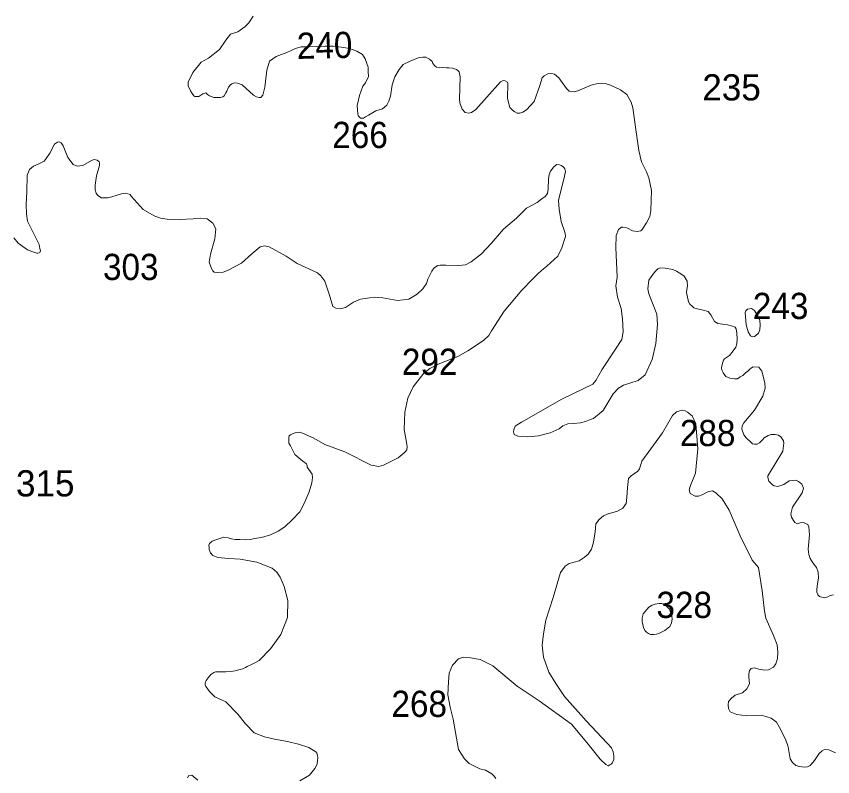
# Model space of a CAD drawing. Extents: x 445.4 to 500, y 8728.7 to 8784.
# Drawn here: x 471.621 to 476.604, y 8779.353 to 8783.996 of the extents above; entities that cross this region are included whole.
import ezdxf
from ezdxf.enums import TextEntityAlignment as Align

# ---------------------------------------------------------------- set-up
doc = ezdxf.new("R2010")
doc.units = 0
doc.header["$LTSCALE"] = 0.064
doc.layers.add('2', color=7, linetype='Continuous', lineweight=13)
doc.layers.add('21', color=7, linetype='Continuous')
doc.layers.add('61', color=7, linetype='Continuous')

msp = doc.modelspace()

# ---------------------------------------------------------------- linework, layer by layer
at = {"layer": '2'}
for points in [[(473.0668, 8783.9956), (473.0406, 8783.9568), (473.0151, 8783.9313), (472.9726, 8783.9016), (472.9286, 8783.8861), (472.8989, 8783.8493), (472.8606, 8783.7927), (472.7941, 8783.7403), (472.7501, 8783.7162), (472.6991, 8783.6526), (472.6708, 8783.5946), (472.6708, 8783.5719), (472.6835, 8783.5408), (472.6949, 8783.5252), (472.7034, 8783.5111), (472.7105, 8783.5068), (472.7345, 8783.5068), (472.7602, 8783.5219), (472.7772, 8783.5276), (472.7885, 8783.5177), (472.7999, 8783.5106), (472.8268, 8783.4993), (472.8452, 8783.4993), (472.8679, 8783.5007), (472.8806, 8783.505), (472.8891, 8783.5106), (472.8891, 8783.5106), (472.9004, 8783.5276), (472.9061, 8783.5389), (472.916, 8783.563), (472.9274, 8783.5771), (472.9359, 8783.5842), (472.9529, 8783.5899), (472.9699, 8783.587), (472.9699, 8783.587), (472.9996, 8783.5771), (473.069, 8783.5135), (473.086, 8783.505), (473.1002, 8783.5007), (473.1129, 8783.4993), (473.1257, 8783.5135), (473.1384, 8783.563), (473.1498, 8783.6663), (473.1668, 8783.7215), (473.2065, 8783.7512), (473.2716, 8783.7738), (473.3259, 8783.7987), (473.3585, 8783.8086), (473.3996, 8783.8086), (473.4506, 8783.8114), (473.5058, 8783.8143), (473.5554, 8783.8143), (473.6064, 8783.8072), (473.6546, 8783.7987), (473.6985, 8783.7831), (473.7339, 8783.7619), (473.7509, 8783.7365), (473.7686, 8783.6846), (473.7686, 8783.6578), (473.77, 8783.628), (473.7516, 8783.5898), (473.736, 8783.5686), (473.7162, 8783.512), (473.702, 8783.4512), (473.7062, 8783.3974), (473.7091, 8783.3861), (473.7218, 8783.3733), (473.7402, 8783.3747), (473.7516, 8783.3818), (473.7714, 8783.3917), (473.8153, 8783.4186), (473.855, 8783.4313), (473.8833, 8783.454), (473.8947, 8783.4766), (473.9046, 8783.5078), (473.9159, 8783.5771), (473.9315, 8783.6266), (473.9584, 8783.6719), (473.9825, 8783.7016), (474.025, 8783.7214), (474.0746, 8783.7413), (474.1015, 8783.7455), (474.1199, 8783.7455), (474.1426, 8783.7342), (474.1582, 8783.72), (474.1638, 8783.7073), (474.1752, 8783.6931), (474.1865, 8783.6846), (474.2035, 8783.6804), (474.2219, 8783.6832), (474.246, 8783.6818), (474.2616, 8783.6818), (474.2828, 8783.679), (474.3083, 8783.6705), (474.3083, 8783.6705), (474.3183, 8783.6634), (474.3239, 8783.6563), (474.3306, 8783.6262), (474.3249, 8783.489), (474.3277, 8783.4678), (474.3419, 8783.4281)], [(474.3419, 8783.4281), (474.3603, 8783.4083), (474.383, 8783.4041), (474.3986, 8783.4083), (474.4255, 8783.4267), (474.5757, 8783.5965), (474.5757, 8783.5965), (474.5927, 8783.6036), (474.6054, 8783.6008), (474.6182, 8783.5937), (474.621, 8783.5866), (474.6182, 8783.4932), (474.6337, 8783.438), (474.6465, 8783.4253), (474.6592, 8783.4154), (474.6777, 8783.4041), (474.6947, 8783.4041), (474.7131, 8783.4097), (474.7357, 8783.4253), (474.7811, 8783.4762), (474.8165, 8783.5725), (474.8307, 8783.6206), (474.8434, 8783.6319), (474.8647, 8783.6446), (474.8882, 8783.6462), (474.9066, 8783.6434), (474.9321, 8783.6194), (474.9789, 8783.5557), (474.9959, 8783.5387), (474.9959, 8783.5387), (475.0256, 8783.5345), (475.0483, 8783.5415), (475.1304, 8783.5755), (475.163, 8783.584), (475.1914, 8783.5882), (475.214, 8783.5854), (475.2466, 8783.5755), (475.3089, 8783.5472), (475.3472, 8783.5175), (475.3741, 8783.4722), (475.3829, 8783.4374), (475.4041, 8783.2903), (475.4197, 8783.1756), (475.4367, 8783.1063), (475.4665, 8783.0469), (475.481, 8783.0105), (475.498, 8782.9313), (475.4937, 8782.811), (475.4866, 8782.7742), (475.4668, 8782.7346), (475.4413, 8782.6936), (475.4328, 8782.6865), (475.4101, 8782.6822), (475.3818, 8782.6851), (475.3506, 8782.702), (475.3421, 8782.7063), (475.3237, 8782.7091), (475.3138, 8782.7077), (475.2954, 8782.6936), (475.2826, 8782.6568), (475.281, 8782.5836), (475.2881, 8782.4025), (475.2796, 8782.3501), (475.2895, 8782.2808), (475.3122, 8782.2114), (475.3207, 8782.148), (475.325, 8782.0702), (475.3165, 8782.0235), (475.2782, 8781.9627), (475.1947, 8781.8367), (475.1578, 8781.773), (475.1388, 8781.7507), (474.9504, 8781.6588), (474.7039, 8781.5173), (474.6656, 8781.4932), (474.6585, 8781.4706), (474.6557, 8781.4578), (474.6595, 8781.4431), (474.6595, 8781.4431), (474.6828, 8781.4314), (474.7412, 8781.4285), (474.8083, 8781.4343), (474.8784, 8781.4518), (474.9338, 8781.4781), (474.9572, 8781.4956), (474.9864, 8781.5072), (475.0214, 8781.5101), (475.0651, 8781.5131), (475.0943, 8781.5218), (475.1264, 8781.5335), (475.1439, 8781.5393), (475.2023, 8781.5888), (475.2636, 8781.6909), (475.2957, 8781.7259), (475.3278, 8781.743), (475.4166, 8781.7731), (475.4595, 8781.8064), (475.5023, 8781.9014), (475.5234, 8781.9974), (475.5345, 8782.1147), (475.5297, 8782.1765)], [(474.3217, 8782.4741), (474.243, 8782.4754), (474.2082, 8782.4767), (474.1927, 8782.4741), (474.1707, 8782.46), (474.1565, 8782.4406), (474.1333, 8782.3903), (474.1251, 8782.3643), (474.1031, 8782.332), (474.0683, 8782.2998), (474.0166, 8782.2689), (473.9482, 8782.2599), (473.8579, 8782.2766), (473.8101, 8782.2805), (473.7779, 8782.2779), (473.7211, 8782.2689), (473.6798, 8782.2495), (473.6295, 8782.2186), (473.5985, 8782.2096), (473.5714, 8782.2134), (473.552, 8782.2238), (473.5314, 8782.2985), (473.5046, 8782.3788), (473.4788, 8782.411), (473.4582, 8782.4303), (473.3343, 8782.487), (473.2672, 8782.5309), (473.1639, 8782.5889), (473.1381, 8782.5953), (473.1097, 8782.5889), (473.0581, 8782.5451), (472.9961, 8782.4883), (472.9097, 8782.4432), (472.8833, 8782.4343), (472.8497, 8782.4318), (472.8278, 8782.433), (472.82, 8782.4408), (472.8123, 8782.455), (472.7981, 8782.4949), (472.8071, 8782.5439), (472.8316, 8782.6367), (472.8381, 8782.6981), (472.82, 8782.7329), (472.7865, 8782.7587), (472.7439, 8782.7626), (472.7013, 8782.76), (472.6161, 8782.7561), (472.5419, 8782.7564), (472.5019, 8782.7629), (472.4619, 8782.7771), (472.3961, 8782.817), (472.3225, 8782.897), (472.3148, 8782.9086), (472.2864, 8782.9163), (472.2631, 8782.9124), (472.2038, 8782.8944), (472.1779, 8782.8879), (472.14, 8782.8871), (472.1193, 8782.9025), (472.109, 8782.9154), (472.1025, 8782.9361), (472.1025, 8782.9644), (472.1103, 8783.0224), (472.1284, 8783.0843), (472.1284, 8783.0985), (472.1271, 8783.1062), (472.1142, 8783.1178), (472.0961, 8783.1217), (472.0793, 8783.1153), (472.0277, 8783.0843), (472.0083, 8783.083), (471.9915, 8783.0817), (471.9683, 8783.0908), (471.9361, 8783.1346), (471.9064, 8783.2042), (471.8948, 8783.2235), (471.8818, 8783.2287), (471.8715, 8783.2274), (471.8715, 8783.2274), (471.8543, 8783.2158), (471.8246, 8783.1603), (471.8039, 8783.1268), (471.791, 8783.1113), (471.7536, 8783.0933), (471.7265, 8783.0817), (471.702, 8783.0598), (471.6865, 8783.0263), (471.6852, 8782.9231), (471.6813, 8782.8462), (471.6826, 8782.7895), (471.689, 8782.7444), (471.711, 8782.6993), (471.7394, 8782.6425), (471.7613, 8782.6026), (471.7639, 8782.5781), (471.7677, 8782.5639), (471.7671, 8782.5573), (471.7651, 8782.5537), (471.7605, 8782.5507), (471.7528, 8782.5496), (471.7452, 8782.5496)], [(472.8438, 8780.8024), (472.8878, 8780.8157), (472.9145, 8780.8116), (472.9339, 8780.8045), (472.9565, 8780.8024), (472.9851, 8780.8024), (473.0189, 8780.8004), (473.0497, 8780.8024), (473.0753, 8780.8076), (473.1173, 8780.8127), (473.1726, 8780.8301), (473.2194, 8780.8521), (473.2604, 8780.8787), (473.3054, 8780.9206), (473.3505, 8780.9708), (473.3782, 8781.0219), (473.4089, 8781.0925), (473.4243, 8781.1478), (473.4285, 8781.1802), (473.4264, 8781.1996), (473.3967, 8781.2436), (473.3967, 8781.2508), (473.3937, 8781.2569), (473.3916, 8781.2641), (473.3691, 8781.2794), (473.3199, 8781.3214), (473.2953, 8781.3736), (473.2851, 8781.3899), (473.2851, 8781.4237), (473.2861, 8781.4339), (473.2943, 8781.4411), (473.3066, 8781.4472), (473.322, 8781.4534), (473.3342, 8781.4554), (473.3486, 8781.4564), (473.367, 8781.4503), (473.4367, 8781.4196), (473.5043, 8781.3807), (473.6262, 8781.3367), (473.787, 8781.2559), (473.8329, 8781.2462), (473.8482, 8781.2503), (473.8626, 8781.2544), (473.9518, 8781.2991), (473.9877, 8781.3298), (473.999, 8781.34), (474.0041, 8781.3492), (474.0061, 8781.3666), (474.0051, 8781.384), (473.9877, 8781.473), (473.9918, 8781.5782), (474.0102, 8781.6652), (474.044, 8781.7337), (474.1085, 8781.8166), (474.1457, 8781.8458), (474.2051, 8781.8765), (474.3158, 8781.9195), (474.3772, 8781.9543), (474.4725, 8782.0167), (474.5042, 8782.0474), (474.5221, 8782.0747), (474.5989, 8782.1965), (474.7065, 8782.3244), (474.7734, 8782.3926), (474.8061, 8782.4254), (474.8246, 8782.4418), (474.8379, 8782.453), (474.8584, 8782.4694), (474.927, 8782.5308), (474.9506, 8782.5819), (474.9732, 8782.6504), (474.9706, 8782.6711), (474.9461, 8782.7433), (474.9332, 8782.818), (474.9293, 8782.8709), (474.9435, 8782.9302), (474.9628, 8783.0011), (474.9719, 8783.0483), (474.9694, 8783.0638), (474.9655, 8783.0715), (474.9564, 8783.078), (474.9474, 8783.0844), (474.9358, 8783.0896), (474.919, 8783.0909), (474.9022, 8783.0767), (474.8816, 8783.0509), (474.8738, 8783.0303), (474.87, 8783.0006), (474.8674, 8782.9426), (474.8635, 8782.913), (474.848, 8782.8962), (474.8287, 8782.8807), (474.7998, 8782.8592), (474.7352, 8782.8244), (474.6733, 8782.7638), (474.5946, 8782.6968), (474.5197, 8782.6079), (474.4598, 8782.545), (474.3966, 8782.4973), (474.363, 8782.4793), (474.3217, 8782.4741)], [(471.7452, 8782.5496), (471.7217, 8782.5573), (471.6884, 8782.5701), (471.6322, 8782.6104), (471.6049, 8782.6433)], [(475.5297, 8782.1765), (475.4806, 8782.3017), (475.4745, 8782.3325), (475.4824, 8782.3848), (475.4999, 8782.4118), (475.5221, 8782.4387), (475.5364, 8782.4545), (475.5507, 8782.4609), (475.5808, 8782.4577), (475.6284, 8782.4498), (475.6506, 8782.4387), (475.6776, 8782.4228), (475.6966, 8782.4086), (475.7157, 8782.3785), (475.7172, 8782.35), (475.7141, 8782.3278), (475.7109, 8782.3103), (475.722, 8782.2628), (475.7236, 8782.2533), (475.7315, 8782.2374), (475.7458, 8782.2264), (475.7569, 8782.2153), (475.7775, 8782.2105), (475.7966, 8782.2058), (475.814, 8782.2026), (475.8442, 8782.1931), (475.8605, 8782.1729), (475.8827, 8782.1317), (475.9033, 8782.1206), (475.9319, 8782.1159), (475.962, 8782.1111), (475.9922, 8782.1048), (476.008, 8782.0984), (476.0144, 8782.0874), (476.0176, 8782.062), (476.0207, 8782.0256), (476.0176, 8781.9954), (476.0128, 8781.9764), (475.9969, 8781.9527), (475.9731, 8781.9257), (475.943, 8781.9035), (475.9366, 8781.8956), (475.9335, 8781.8845), (475.9271, 8781.8623), (475.9255, 8781.8481), (475.9287, 8781.8306), (475.9351, 8781.8196), (475.9509, 8781.7974), (475.9763, 8781.7863), (475.9938, 8781.7847), (476.0049, 8781.7815), (476.0223, 8781.7831), (476.0302, 8781.7879), (476.0398, 8781.7942), (476.0556, 8781.8037), (476.0715, 8781.818), (476.0858, 8781.8291), (476.0985, 8781.8417), (476.108, 8781.8497), (476.1191, 8781.856), (476.1524, 8781.8544), (476.1524, 8781.8544), (476.1714, 8781.8291), (476.1905, 8781.7578), (476.1923, 8781.7249), (476.1764, 8781.6758), (476.1272, 8781.5918), (476.0622, 8781.5142), (476.0511, 8781.4951), (476.0495, 8781.4745), (476.0606, 8781.4413), (476.0749, 8781.4223), (476.105, 8781.3953), (476.1146, 8781.3858), (476.1257, 8781.3826), (476.1431, 8781.3842), (476.1574, 8781.3921), (476.1748, 8781.4096), (476.1859, 8781.4223), (476.2097, 8781.4365), (476.2272, 8781.4429), (476.2526, 8781.4429), (476.2732, 8781.4381), (476.2875, 8781.4286), (476.3033, 8781.4048), (476.3049, 8781.389), (476.2986, 8781.3399), (476.2529, 8781.2628), (476.2085, 8781.1899), (476.2069, 8781.1804), (476.2148, 8781.1582), (476.2355, 8781.136), (476.2466, 8781.1297), (476.2688, 8781.1249), (476.3053, 8781.1376), (476.3386, 8781.1598), (476.3782, 8781.1629), (476.3957, 8781.155), (476.4163, 8781.1392), (476.4258, 8781.1154), (476.4179, 8781.0869)], [(475.9718, 8780.9796), (475.9282, 8781.0498), (475.8894, 8781.0861), (475.87, 8781.0982), (475.8409, 8781.0934), (475.807, 8781.074), (475.7852, 8781.0667), (475.7634, 8781.0667), (475.7343, 8781.0813), (475.727, 8781.1055), (475.7367, 8781.1321), (475.7658, 8781.2072), (475.7801, 8781.3541), (475.7682, 8781.508), (475.7454, 8781.5563), (475.717, 8781.579), (475.7042, 8781.5876), (475.6842, 8781.5904), (475.67, 8781.5862), (475.6501, 8781.5805), (475.6259, 8781.5591), (475.5647, 8781.4525), (475.438, 8781.2805), (475.4323, 8781.2592), (475.4252, 8781.2336), (475.4152, 8781.2194), (475.374, 8781.1909), (475.3583, 8781.1739), (475.3512, 8781.1184), (475.348, 8781.0576), (475.3423, 8781.022), (475.3224, 8780.9922), (475.2896, 8780.9737), (475.227, 8780.9566), (475.2042, 8780.9453), (475.1786, 8780.9239), (475.1587, 8780.8969), (475.153, 8780.8486), (475.143, 8780.7846), (475.1316, 8780.742), (475.1117, 8780.7121), (475.0875, 8780.6908), (475.0557, 8780.6712), (474.9959, 8780.6542), (474.9717, 8780.6385), (474.9418, 8780.6002), (474.8977, 8780.448), (474.8536, 8780.3087), (474.8379, 8780.2254), (474.8307, 8780.1572), (474.8379, 8780.0833), (474.872, 8779.9923), (474.9147, 8779.9226), (474.966, 8779.842), (475.0998, 8779.6942), (475.2279, 8779.5577), (475.2535, 8779.5299), (475.2635, 8779.5058), (475.2677, 8779.4816), (475.2677, 8779.4589), (475.2578, 8779.4361), (475.2507, 8779.4304), (475.2435, 8779.4247), (475.2336, 8779.4205), (475.2194, 8779.4276), (475.1838, 8779.4603), (475.1026, 8779.5626), (475.0087, 8779.675), (474.8119, 8779.8167), (474.6781, 8779.9063), (474.5301, 8780.03), (474.4518, 8780.0683), (474.3921, 8780.0797), (474.3479, 8780.084), (474.3195, 8780.0726), (474.2839, 8780.0342), (474.2625, 8779.9845), (474.2583, 8779.9319), (474.2554, 8779.8523), (474.2696, 8779.7783), (474.2863, 8779.7036), (474.3076, 8779.5885), (474.3204, 8779.5202), (474.3574, 8779.4619), (474.3845, 8779.4335), (474.45, 8779.4008), (474.4855, 8779.3923), (474.5225, 8779.371), (474.5368, 8779.3557), (474.5468, 8779.3429)], [(476.4179, 8781.0869), (476.3592, 8780.9981), (476.3513, 8780.9744), (476.3481, 8780.9585), (476.3529, 8780.9379), (476.364, 8780.9173), (476.3735, 8780.9046), (476.3862, 8780.8967), (476.4052, 8780.9031), (476.4258, 8780.9046), (476.4258, 8780.9046), (476.4385, 8780.8999), (476.4385, 8780.8999), (476.4512, 8780.892), (476.4576, 8780.8793), (476.4625, 8780.8304), (476.453, 8780.7433), (476.4582, 8780.7098), (476.4669, 8780.6846), (476.4815, 8780.6584), (476.5039, 8780.6312), (476.5155, 8780.603), (476.5165, 8780.5661), (476.5097, 8780.5185), (476.5078, 8780.4923), (476.5078, 8780.4806), (476.5136, 8780.4632), (476.5223, 8780.4544), (476.5291, 8780.4505), (476.5532, 8780.4459), (476.5736, 8780.4518), (476.5882, 8780.459), (476.6086, 8780.4634)], [(476.6215, 8779.4993), (476.5802, 8779.5177), (476.5538, 8779.5188), (476.54, 8779.5119), (476.5204, 8779.4959), (476.4929, 8779.4523), (476.4653, 8779.4213), (476.4504, 8779.4144), (476.4297, 8779.4121), (476.401, 8779.4155), (476.378, 8779.4224), (476.3585, 8779.4396), (476.3435, 8779.4626), (476.3309, 8779.536), (476.316, 8779.5819), (476.2792, 8779.6542), (476.2597, 8779.6852), (476.2287, 8779.7116), (476.1752, 8779.727), (476.0799, 8779.7247), (476.0179, 8779.7328), (475.9788, 8779.75), (475.9685, 8779.7706), (475.9662, 8779.7924), (475.9673, 8779.8119), (475.9857, 8779.8326), (476.0087, 8779.851), (476.0523, 8779.8647), (476.0799, 8779.89), (476.095, 8779.9195), (476.0927, 8779.9631), (476.0927, 8779.9814), (476.0962, 8780.001), (476.1065, 8780.0147), (476.126, 8780.0182), (476.1536, 8780.009), (476.1892, 8780.0032), (476.2122, 8780.0055), (476.2421, 8780.0228), (476.257, 8780.0423), (476.2662, 8780.0744), (476.2696, 8780.1134), (476.2639, 8780.1582), (476.2421, 8780.2155), (476.196, 8780.3207), (476.1868, 8780.3643), (476.1741, 8780.4871), (476.1513, 8780.6295), (476.1125, 8780.6755), (476.0397, 8780.8246), (475.9718, 8780.9796)], [(473.3522, 8779.3278), (473.4104, 8779.362), (473.4435, 8779.4031), (473.4566, 8779.43), (473.46, 8779.4528), (473.4611, 8779.4688), (473.4589, 8779.4848), (473.4543, 8779.4973), (473.4486, 8779.5041), (473.4064, 8779.5315), (473.3428, 8779.5514), (473.2755, 8779.5685), (473.1967, 8779.5821), (473.1363, 8779.597), (473.0735, 8779.622), (473.0198, 8779.6756), (472.973, 8779.7349), (472.8988, 8779.8102), (472.8332, 8779.8415), (472.8001, 8779.8734), (472.7853, 8779.8939), (472.7784, 8779.9042), (472.7739, 8779.9133), (472.7739, 8779.9236), (472.775, 8779.9329), (472.7801, 8779.9416), (472.7909, 8779.956), (472.8088, 8779.978), (472.8262, 8779.9898), (472.8375, 8779.9944), (472.8601, 8779.9944), (472.899, 8779.9934), (472.9272, 8779.9965), (472.9569, 8779.999), (472.9795, 8780.0062), (473.0025, 8780.0124), (473.02, 8780.0206), (473.0292, 8780.0257), (473.0558, 8780.0375), (473.0845, 8780.0518), (473.103, 8780.0628), (473.1729, 8780.1346), (473.2348, 8780.2224), (473.2757, 8780.3257), (473.2777, 8780.4294), (473.255, 8780.5153), (473.2314, 8780.5716), (473.2109, 8780.6023), (473.1823, 8780.6258), (473.088, 8780.6626), (472.9866, 8780.6821), (472.9155, 8780.6848), (472.8509, 8780.6919), (472.8212, 8780.7042), (472.8069, 8780.7196), (472.8018, 8780.7308), (472.7987, 8780.741), (472.7977, 8780.7533), (472.7967, 8780.7666), (472.8008, 8780.7779), (472.8171, 8780.7912), (472.8438, 8780.8024)], [(472.6655, 8779.3472), (472.6746, 8779.3609), (472.6929, 8779.362), (472.7294, 8779.3324)]]:
    msp.add_lwpolyline(points, dxfattribs=at)
for points in [[(476.1076, 8782.212), (476.0844, 8782.2073), (476.0728, 8782.1981), (476.0693, 8782.1865), (476.0751, 8782.1113), (476.0879, 8782.0685), (476.1029, 8782.0454), (476.1134, 8782.0385), (476.1273, 8782.0408), (476.1342, 8782.0477), (476.1504, 8782.0604), (476.1585, 8782.0824), (476.162, 8782.1125), (476.1597, 8782.1379), (476.1493, 8782.1611), (476.1273, 8782.2004)], [(475.4465, 8780.3483), (475.4811, 8780.3893), (475.5027, 8780.4001), (475.52, 8780.4066), (475.5319, 8780.4088), (475.5449, 8780.4099), (475.56, 8780.4099), (475.5784, 8780.4012), (475.5914, 8780.3926), (475.6076, 8780.3753), (475.6217, 8780.3353), (475.6239, 8780.3148), (475.6206, 8780.2932), (475.6087, 8780.2694), (475.5795, 8780.2456), (475.559, 8780.2359), (475.5417, 8780.2273), (475.5276, 8780.224), (475.5114, 8780.2219), (475.4919, 8780.2219), (475.4789, 8780.2273), (475.467, 8780.2359), (475.4573, 8780.2467), (475.4497, 8780.264), (475.4454, 8780.2824), (475.441, 8780.3018), (475.441, 8780.3224)]]:
    msp.add_lwpolyline(points, close=True, dxfattribs=at)

# ---------------------------------------------------------------- texts
at = {"layer": '21'}
for s, p in [('235', (475.8078, 8783.4819)), ('315', (471.6189, 8781.0643))]:
    msp.add_text(s, height=0.16, dxfattribs=at).set_placement(p)
at = {"layer": '21', "width": 0.95}
for s, p in [('266', (473.5493, 8783.1915)), ('303', (472.1498, 8782.3856)), ('243', (476.1161, 8782.1475)), ('292', (473.974, 8781.8065)), ('288', (475.671, 8781.3716)), ('328', (475.528, 8780.3224)), ('268', (473.9104, 8779.7182))]:
    msp.add_text(s, height=0.16, dxfattribs=at).set_placement(p)
at = {"layer": '61', "width": 0.95}
msp.add_text('240', height=0.16, rotation=1.155, dxfattribs=at).set_placement((473.5039, 8783.7387), align=Align.CENTER)

doc.saveas('drawing.dxf')
